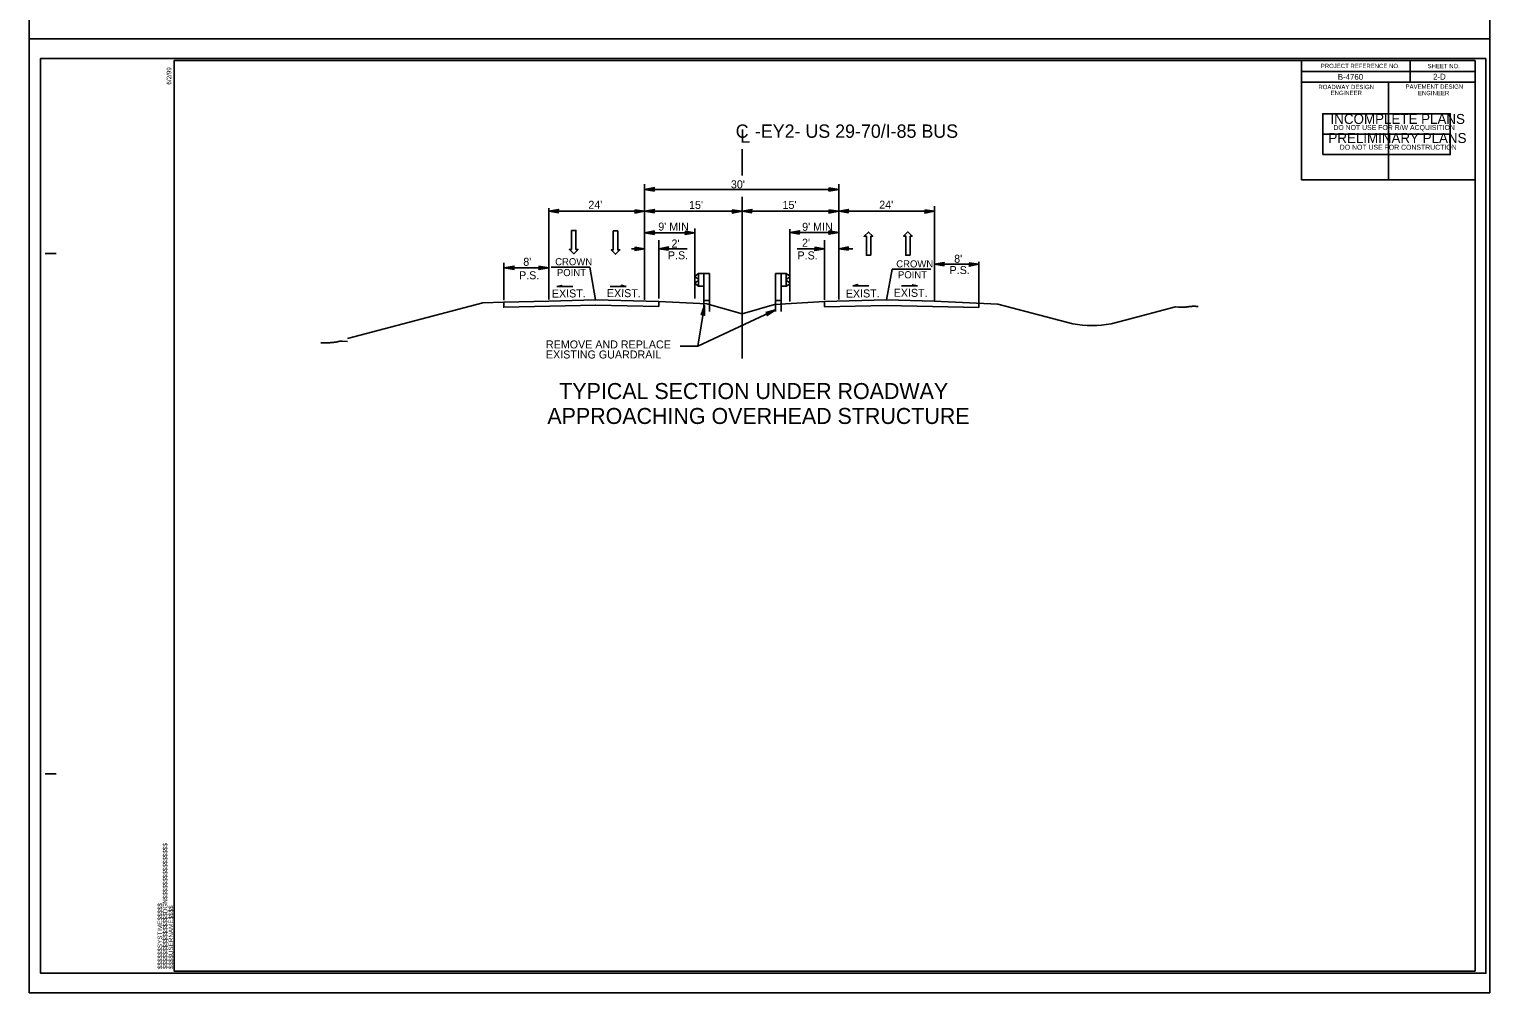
# Model space of a CAD drawing. Extents: x 981824 to 982276, y 44828 to 45204.
# Drawn here: x 981823.9 to 981958.6, y 44827.6 to 44916.4 of the extents above; entities that cross this region are included whole.
import ezdxf

# ---------------------------------------------------------------- set-up
doc = ezdxf.new("R2010")
doc.units = 0
for name, color, linetype in [('Old_Level_1', 7, 'Continuous'), ('Old_Level_11', 7, 'Continuous'), ('Old_Level_18', 7, 'Continuous'), ('Old_Level_3', 7, 'Continuous'), ('Old_Level_4', 7, 'Continuous'), ('Old_Level_40', 7, 'Continuous'), ('Old_Level_41', 7, 'Continuous'), ('Old_Level_44', 7, 'Continuous'), ('Old_Level_50', 7, 'Continuous'), ('Old_Level_51', 7, 'Continuous'), ('Old_Level_52', 7, 'Continuous'), ('Prop Dimension Text', 7, 'Continuous'), ('Prop Terminator CELL', 7, 'Continuous'), ('Sheet Sticker Incomplete CELL', 7, 'Continuous'), ('Sheet Sticker Preliminary CELL', 7, 'Continuous'), ('Typical Guardrail CELL', 7, 'Continuous')]:
    doc.layers.add(name, color=color, linetype=linetype)

msp = doc.modelspace()

# ---------------------------------------------------------------- linework, layer by layer
at = {"layer": 'Old_Level_1'}
for p, q in [((981958.24, 44913.76), (981958.24, 44913.76)), ((981889.63, 44902.96), (981889.63, 44905.39)), ((981889.63, 44886.06), (981889.63, 44901)), ((981867.69, 44894.43), (981871.8, 44894.43)), ((981876.12, 44891.47), (981875.58, 44894.51)), ((981902.95, 44891.47), (981903.48, 44894.31)), ((981907.38, 44894.76), (981911.47, 44894.76)), ((981924.96, 44889.6), (981923.66, 44889.26))]:
    msp.add_line(p, q, dxfattribs=at)
at = {"layer": 'Old_Level_11'}
for p, q in [((981880.64, 44891.48), (981880.64, 44902.15)), ((981880.64, 44901.67), (981889.63, 44901.67)), ((981889.63, 44901.67), (981898.54, 44901.67)), ((981898.54, 44891.51), (981898.54, 44902.14)), ((981871.8, 44891.5), (981871.8, 44899.95)), ((981871.8, 44899.65), (981880.64, 44899.65)), ((981880.64, 44899.65), (981889.63, 44899.65)), ((981889.63, 44899.65), (981898.54, 44899.65)), ((981907.38, 44899.65), (981898.54, 44899.65)), ((981907.38, 44891.43), (981907.38, 44900.11)), ((981880.64, 44897.67), (981885.28, 44897.67)), ((981881.94, 44891.62), (981881.94, 44896.99)), ((981885.28, 44891.62), (981885.28, 44898.05)), ((981894.04, 44891.32), (981894.04, 44897.99)), ((981894.04, 44897.7), (981898.54, 44897.7)), ((981897.23, 44891.48), (981897.23, 44896.99)), ((981879.42, 44896.2), (981880.64, 44896.2)), ((981881.94, 44896.2), (981884.57, 44896.2)), ((981897.23, 44896.2), (981894.72, 44896.2)), ((981899.86, 44896.2), (981898.54, 44896.2)), ((981867.64, 44891.44), (981867.64, 44894.89)), ((981911.47, 44891.25), (981911.47, 44894.98)), ((981865.71, 44891.22), (981853.23, 44887.93)), ((981865.71, 44891.22), (981867.64, 44891.28)), ((981867.64, 44891.28), (981871.81, 44891.37)), ((981886.37, 44891.12), (981889.63, 44890.18)), ((981892.62, 44891.05), (981889.63, 44890.18)), ((981897.22, 44891.33), (981897.22, 44890.84)), ((981907.36, 44891.36), (981913.22, 44891.08)), ((981911.47, 44891.16), (981911.47, 44890.77)), ((981913.22, 44891.08), (981917.69, 44889.9)), ((981929.62, 44890.83), (981924.96, 44889.6)), ((981917.69, 44889.9), (981920.14, 44889.26))]:
    msp.add_line(p, q, dxfattribs=at)
for points in [[(981881.54, 44901.52), (981880.64, 44901.67), (981881.54, 44901.84), (981881.43, 44901.67)], [(981897.64, 44901.82), (981898.54, 44901.67), (981897.64, 44901.51), (981897.75, 44901.67)], [(981872.7, 44899.51), (981871.8, 44899.65), (981872.7, 44899.82), (981872.58, 44899.65)], [(981879.74, 44899.8), (981880.64, 44899.65), (981879.74, 44899.49), (981879.85, 44899.65)], [(981881.54, 44899.51), (981880.64, 44899.65), (981881.54, 44899.82), (981881.43, 44899.65)], [(981888.73, 44899.8), (981889.63, 44899.65), (981888.73, 44899.49), (981888.84, 44899.65)], [(981890.53, 44899.51), (981889.63, 44899.65), (981890.53, 44899.82), (981890.42, 44899.65)], [(981897.64, 44899.8), (981898.54, 44899.65), (981897.64, 44899.49), (981897.75, 44899.65)], [(981899.44, 44899.51), (981898.54, 44899.65), (981899.44, 44899.82), (981899.33, 44899.65)], [(981906.48, 44899.8), (981907.38, 44899.65), (981906.48, 44899.49), (981906.6, 44899.65)], [(981881.54, 44897.52), (981880.64, 44897.67), (981881.54, 44897.84), (981881.43, 44897.67)], [(981884.38, 44897.82), (981885.28, 44897.67), (981884.38, 44897.51), (981884.5, 44897.67)], [(981894.94, 44897.55), (981894.04, 44897.7), (981894.94, 44897.86), (981894.82, 44897.7)], [(981897.64, 44897.85), (981898.54, 44897.7), (981897.64, 44897.53), (981897.75, 44897.7)], [(981879.74, 44896.35), (981880.64, 44896.2), (981879.74, 44896.04), (981879.85, 44896.2)], [(981882.85, 44896.06), (981881.94, 44896.2), (981882.85, 44896.37), (981882.73, 44896.2)], [(981896.33, 44896.34), (981897.23, 44896.2), (981896.33, 44896.03), (981896.45, 44896.2)], [(981899.44, 44896.05), (981898.54, 44896.2), (981899.44, 44896.36), (981899.33, 44896.2)], [(981868.6, 44894.29), (981867.69, 44894.43), (981868.6, 44894.6), (981868.48, 44894.43)], [(981870.89, 44894.58), (981871.8, 44894.43), (981870.89, 44894.27), (981871.01, 44894.43)], [(981908.28, 44894.61), (981907.38, 44894.76), (981908.28, 44894.92), (981908.17, 44894.76)], [(981910.57, 44894.9), (981911.47, 44894.76), (981910.57, 44894.59), (981910.69, 44894.76)]]:
    msp.add_lwpolyline(points, close=True, dxfattribs=at)
for points in [[(981871.81, 44891.37), (981876.12, 44891.47)], [(981881.95, 44891.34), (981876.12, 44891.47)], [(981897.22, 44891.33), (981902.95, 44891.47)], [(981907.36, 44891.36), (981902.95, 44891.47)], [(981867.64, 44891.28), (981867.65, 44890.8), (981876.13, 44891)], [(981881.95, 44891.34), (981881.94, 44890.87), (981876.11, 44891)], [(981881.95, 44891.34), (981886.37, 44891.12)], [(981897.22, 44891.33), (981892.62, 44891.05)], [(981897.22, 44890.84), (981902.92, 44890.97)], [(981911.47, 44890.77), (981902.92, 44890.97)], [(981929.62, 44890.83), (981929.87, 44890.82), (981929.91, 44890.82), (981929.94, 44890.81), (981929.96, 44890.81), (981930.01, 44890.82), (981930.05, 44890.82), (981930.1, 44890.82), (981930.13, 44890.82), (981930.19, 44890.81), (981930.24, 44890.81), (981930.3, 44890.81), (981930.36, 44890.81), (981930.43, 44890.82), (981930.5, 44890.82), (981930.55, 44890.82), (981930.6, 44890.82), (981930.64, 44890.83), (981930.7, 44890.84), (981930.74, 44890.84), (981930.81, 44890.85), (981930.86, 44890.86), (981930.96, 44890.87), (981931.01, 44890.88), (981931.08, 44890.88), (981931.12, 44890.88), (981931.17, 44890.89), (981931.2, 44890.89), (981931.27, 44890.89), (981931.33, 44890.9), (981931.37, 44890.9), (981931.43, 44890.9), (981931.46, 44890.89), (981931.52, 44890.88), (981931.55, 44890.88), (981931.61, 44890.87), (981931.65, 44890.87), (981931.7, 44890.86)], [(981853.24, 44887.65), (981852.74, 44887.67), (981852.68, 44887.67), (981852.63, 44887.67), (981852.58, 44887.67), (981852.54, 44887.67), (981852.52, 44887.66), (981852.49, 44887.66), (981852.46, 44887.64), (981852.41, 44887.64), (981852.38, 44887.63), (981852.32, 44887.61), (981852.3, 44887.61), (981852.24, 44887.6), (981852.21, 44887.59), (981852.17, 44887.59), (981852.13, 44887.57), (981852.09, 44887.57), (981852.05, 44887.57), (981852.02, 44887.57), (981851.97, 44887.56), (981851.95, 44887.56), (981851.9, 44887.56), (981851.86, 44887.55), (981851.8, 44887.55), (981851.76, 44887.55), (981851.68, 44887.55), (981851.64, 44887.53), (981851.55, 44887.52), (981851.5, 44887.52), (981851.44, 44887.52), (981851.36, 44887.52), (981851.31, 44887.52), (981851.24, 44887.52), (981851.2, 44887.52), (981851.11, 44887.52), (981851.09, 44887.52), (981851.03, 44887.52), (981850.99, 44887.52), (981850.93, 44887.52), (981850.89, 44887.53), (981850.84, 44887.53), (981850.81, 44887.53), (981850.79, 44887.53)]]:
    msp.add_lwpolyline(points, dxfattribs=at)
msp.add_arc((981921.9, 44898.38), 9.28, 259.0538, 280.9462, dxfattribs=at)
at = {"layer": 'Old_Level_18'}
msp.add_line((981837.24, 44829.55), (981837.24, 44829.55), dxfattribs=at)
msp.add_line((981837.24, 44829.55), (981837.24, 44829.55), dxfattribs=at)
msp.add_lwpolyline([(981957.24, 44913.55), (981837.24, 44913.55), (981837.24, 44829.55), (981957.24, 44829.55)], close=True, dxfattribs=at)
at = {"layer": 'Old_Level_3'}
for p, q in [((981872.03, 44894.51), (981875.58, 44894.51)), ((981903.48, 44894.31), (981907.04, 44894.31))]:
    msp.add_line(p, q, dxfattribs=at)
at = {"layer": 'Old_Level_4'}
for p, q in [((981901.33, 44892.78), (981899.85, 44892.78)), ((981904.32, 44892.77), (981905.8, 44892.77)), ((981874.02, 44892.7), (981872.55, 44892.7)), ((981877.46, 44892.72), (981878.94, 44892.72))]:
    msp.add_line(p, q, dxfattribs=at)
for points in [[(981873.89, 44897.89), (981873.89, 44896.13), (981873.71, 44896.13), (981874.1, 44895.74), (981874.51, 44896.13), (981874.3, 44896.13), (981874.3, 44897.89)], [(981877.75, 44897.84), (981877.75, 44896.08), (981877.56, 44896.08), (981877.95, 44895.69), (981878.36, 44896.08), (981878.16, 44896.08), (981878.16, 44897.84)], [(981901.51, 44895.59), (981901.51, 44897.35), (981901.69, 44897.35), (981901.3, 44897.74), (981900.89, 44897.35), (981901.1, 44897.35), (981901.1, 44895.59)], [(981905.14, 44895.59), (981905.14, 44897.36), (981905.32, 44897.36), (981904.93, 44897.75), (981904.52, 44897.36), (981904.73, 44897.36), (981904.73, 44895.59)], [(981872.55, 44892.7), (981873, 44892.81), (981872.92, 44892.7)], [(981878.94, 44892.72), (981878.49, 44892.82), (981878.57, 44892.72)], [(981899.85, 44892.78), (981900.3, 44892.89), (981900.22, 44892.78)], [(981905.8, 44892.77), (981905.35, 44892.88), (981905.43, 44892.77)]]:
    msp.add_lwpolyline(points, close=True, dxfattribs=at)
at = {"layer": 'Old_Level_40'}
for p, q in [((981951.24, 44913.55), (981951.24, 44911.55)), ((981941.23, 44912.55), (981957.24, 44912.55)), ((981949.24, 44911.55), (981949.24, 44902.55)), ((981837.24, 44829.55), (981837.24, 44829.55)), ((981837.24, 44829.55), (981837.24, 44829.55)), ((981837.24, 44829.55), (981837.24, 44829.55)), ((981837.24, 44829.55), (981837.24, 44829.55))]:
    msp.add_line(p, q, dxfattribs=at)
for points in [[(981941.23, 44913.55), (981957.24, 44913.55), (981957.24, 44911.55), (981941.23, 44911.55)], [(981941.23, 44911.55), (981949.24, 44911.55), (981949.24, 44902.55), (981941.23, 44902.55)], [(981949.24, 44911.55), (981957.24, 44911.55), (981957.24, 44902.55), (981949.24, 44902.55)]]:
    msp.add_lwpolyline(points, close=True, dxfattribs=at)
at = {"layer": 'Old_Level_41'}
for p, q in [((981825.36, 44895.75), (981826.36, 44895.75)), ((981825.36, 44847.75), (981826.36, 44847.75))]:
    msp.add_line(p, q, dxfattribs=at)
msp.add_lwpolyline([(981840.24, 44829.55), (981840.24, 44829.55)], dxfattribs=at)
at = {"layer": 'Old_Level_50'}
for p, q in [((981823.88, 44915.55), (981823.88, 44915.55)), ((981958.6, 44915.55), (981958.6, 44915.55)), ((981823.88, 44827.55), (981823.88, 44827.55))]:
    msp.add_line(p, q, dxfattribs=at)
msp.add_lwpolyline([(981958.24, 44913.76), (981824.92, 44913.76), (981824.92, 44829.35), (981958.24, 44829.35)], close=True, dxfattribs=at)
at = {"layer": 'Old_Level_51'}
for points in [[(981958.6, 45003.55), (981823.88, 45003.55), (981823.88, 44915.55), (981958.6, 44915.55)], [(981958.6, 44915.55), (981823.88, 44915.55), (981823.88, 44827.55), (981958.6, 44827.55)]]:
    msp.add_lwpolyline(points, close=True, dxfattribs=at)
at = {"layer": 'Old_Level_52'}
for p, q in [((981958.24, 44913.76), (981958.24, 44913.76)), ((981824.92, 44829.35), (981824.92, 44829.35))]:
    msp.add_line(p, q, dxfattribs=at)
at = {"layer": 'Prop Terminator CELL'}
for points in [[(981885.85, 44890.1), (981886.15, 44890.97), (981886.16, 44890.05), (981886.02, 44890.19)], [(981891.82, 44890.32), (981892.7, 44890.56), (981891.95, 44890.03), (981891.99, 44890.23)]]:
    msp.add_lwpolyline(points, close=True, dxfattribs=at)
at = {"layer": 'Sheet Sticker Incomplete CELL'}
msp.add_lwpolyline([(981943.19, 44906.77), (981943.19, 44908.65), (981954.95, 44908.65), (981954.95, 44906.77)], close=True, dxfattribs=at)
at = {"layer": 'Sheet Sticker Preliminary CELL'}
msp.add_lwpolyline([(981943.19, 44904.89), (981943.19, 44906.77), (981954.95, 44906.77), (981954.95, 44904.89)], close=True, dxfattribs=at)
at = {"layer": 'Typical Guardrail CELL'}
for p, q in [((981885.62, 44893.91), (981885.33, 44893.71)), ((981885.62, 44893.38), (981885.33, 44893.58)), ((981885.62, 44893.28), (981885.33, 44893.08)), ((981885.62, 44892.75), (981885.33, 44892.95)), ((981886.11, 44893.91), (981885.62, 44893.91)), ((981885.62, 44893.91), (981885.62, 44892.75)), ((981885.62, 44893.33), (981885.62, 44893.38)), ((981885.62, 44893.33), (981885.62, 44893.28)), ((981886.11, 44892.75), (981885.62, 44892.75)), ((981886.11, 44893.91), (981886.11, 44891.42)), ((981886.11, 44893.91), (981886.61, 44893.91)), ((981886.61, 44893.91), (981886.61, 44891.42)), ((981893.22, 44893.9), (981892.72, 44893.9)), ((981892.72, 44893.9), (981892.72, 44891.41)), ((981893.22, 44893.9), (981893.22, 44891.41)), ((981893.22, 44893.9), (981893.71, 44893.9)), ((981893.71, 44893.9), (981893.71, 44892.74)), ((981893.71, 44893.9), (981894, 44893.7)), ((981893.71, 44893.37), (981894, 44893.57)), ((981893.71, 44893.32), (981893.71, 44893.37)), ((981893.71, 44893.32), (981893.71, 44893.27)), ((981893.71, 44893.27), (981894, 44893.07)), ((981893.71, 44892.74), (981894, 44892.94)), ((981886.11, 44891.42), (981886.61, 44891.42)), ((981886.11, 44891.42), (981886.11, 44890.42)), ((981886.61, 44891.42), (981886.61, 44890.42)), ((981893.22, 44891.41), (981892.72, 44891.41)), ((981892.72, 44891.41), (981892.72, 44890.4)), ((981893.22, 44892.74), (981893.71, 44892.74)), ((981893.22, 44891.41), (981893.22, 44890.4)), ((981885.54, 44887.22), (981892.7, 44890.56))]:
    msp.add_line(p, q, dxfattribs=at)
msp.add_lwpolyline([(981883.93, 44887.22), (981885.54, 44887.22), (981886.15, 44890.97)], dxfattribs=at)
for centre, start, end in [((981885.37, 44893.64), 125.003, 235.0112), ((981885.37, 44893.02), 125.0059, 235.0366), ((981893.96, 44893.63), 304.9888, 54.997), ((981893.96, 44893.01), 304.9634, 54.9941)]:
    msp.add_arc(centre, 0.0776, start, end, dxfattribs=at)

# ---------------------------------------------------------------- texts
at = {"layer": 'Old_Level_1'}
for s, height, p in [('C', 1.23, (981889.04, 44906.43)), ('-EY2- US 29-70/I-85 BUS', 1.2303, (981890.81, 44906.43)), ('L', 1.23, (981889.46, 44905.97))]:
    msp.add_text(s, height=height, rotation=360, dxfattribs=at).set_placement(p)
for s, p in [('  TYPICAL SECTION UNDER ROADWAY ', (981871.67, 44882.33)), ('APPROACHING OVERHEAD STRUCTURE', (981871.67, 44880.03))]:
    msp.add_text(s, height=1.4764, dxfattribs=at).set_placement(p)
at = {"layer": 'Old_Level_11'}
for s, height, rotation, p in [("30'", 0.738, 360, (981888.6, 44901.77)), ("24'", 0.738, 360, (981875.45, 44899.88)), ("15'", 0.738, 360, (981884.74, 44899.87)), ("15'", 0.738, 360, (981893.36, 44899.87)), ("24'", 0.738, 360, (981902.28, 44899.89)), ("9' MIN", 0.738, 360, (981881.9, 44897.87)), ("9' MIN", 0.738, 360, (981895.17, 44897.85)), ("2'", 0.738, 360, (981883.12, 44896.31)), ("2'", 0.738, 360, (981895.16, 44896.38)), ('P.S.', 0.738, 360, (981882.79, 44895.22)), ('P.S.', 0.738, 360, (981894.74, 44895.21)), ("8'", 0.738, 360, (981909.19, 44894.9)), ('P.S.', 0.738, 360, (981869.06, 44893.38)), ("8'", 0.738, 360, (981869.45, 44894.62)), ('P.S.', 0.738, 360, (981908.77, 44893.86)), ('EXIST.', 0.738, 0.3438, (981872.09, 44891.69)), ('EXIST.', 0.738, 359.6562, (981877.16, 44891.74)), ('EXIST.', 0.738, 0.3438, (981899.2, 44891.69)), ('EXIST.', 0.738, 359.6562, (981903.61, 44891.77)), ('REMOVE AND REPLACE ', 0.7382, 360, (981871.54, 44887)), ('EXISTING GUARDRAIL', 0.7382, 360, (981871.54, 44886.07))]:
    msp.add_text(s, height=height, rotation=rotation, dxfattribs=at).set_placement(p)
at = {"layer": 'Old_Level_41'}
for s, p in [('6/2/99', (981836.98, 44911.33)), ('$$$$$$$$$$$$$$$$DGN$$$$$$$$$$$$$$$$', (981836.62, 44829.74)), ('$$$$$$SYSTIME$$$$$', (981836.14, 44829.74)), ('$$$$USERNAME$$$$', (981837.15, 44829.74))]:
    msp.add_text(s, height=0.42, rotation=90, dxfattribs=at).set_placement(p)
at = {"layer": 'Old_Level_44'}
for s, height, p in [('PROJECT REFERENCE NO.', 0.4, (981943.01, 44912.86)), ('SHEET NO.', 0.4, (981952.86, 44912.85)), (' B-4760', 0.54, (981944.38, 44911.78)), ('2-D', 0.54, (981953.37, 44911.8)), ('ROADWAY DESIGN', 0.4, (981942.79, 44910.92)), ('ENGINEER', 0.4, (981943.92, 44910.37)), ('PAVEMENT DESIGN', 0.4, (981950.83, 44910.95)), ('ENGINEER', 0.4, (981951.97, 44910.36))]:
    msp.add_text(s, height=height, dxfattribs=at).set_placement(p)
at = {"layer": 'Prop Dimension Text'}
for s, p in [('CROWN', (981872.39, 44894.67)), ('POINT', (981872.55, 44893.67)), ('CROWN', (981903.85, 44894.47)), ('POINT', (981904.01, 44893.47))]:
    msp.add_text(s, height=0.656, dxfattribs=at).set_placement(p)
at = {"layer": 'Sheet Sticker Incomplete CELL'}
for s, height, p in [('INCOMPLETE PLANS', 0.9216, (981943.91, 44907.71)), ('DO NOT USE FOR R/W ACQUISITION', 0.4608, (981944.17, 44907.15))]:
    msp.add_text(s, height=height, dxfattribs=at).set_placement(p)
at = {"layer": 'Sheet Sticker Preliminary CELL'}
for s, height, p in [('PRELIMINARY PLANS', 0.9216, (981943.71, 44905.95)), ('DO NOT USE FOR CONSTRUCTION', 0.4608, (981944.76, 44905.33))]:
    msp.add_text(s, height=height, dxfattribs=at).set_placement(p)

doc.saveas('drawing.dxf')
